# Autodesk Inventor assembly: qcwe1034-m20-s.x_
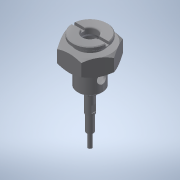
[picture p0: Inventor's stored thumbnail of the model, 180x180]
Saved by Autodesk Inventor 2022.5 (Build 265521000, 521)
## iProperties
Created: 2020-10
Part Number: qcwe1034-m20-s.x_
Material: 一般
Document SubType Name: Assembly
Designer: ImaoCorp
Sending System: SOLIDWORKS 2018-2018316
MC: AMD64
MC_MODEL: Intel64 Family 6 Model 60 Stepping 3, GenuineIntel
OS: Windows_NT
FRU: Parasolid Version 30.0, build 310,  6- 8-2018
FORMAT: text
GUISE: transmit
KEY: qcwe1034-m20-s
FILE: qcwe1034-m20-s.x_t
DATE: Tue Oct  6 10:34:24 2020
Author: ImaoCorp
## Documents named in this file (4)
- X:\14_SW2022-Inv2022\00_全2023-1023新製品(TCC)まで\q\qcwe1034-m20-s\QCWE1034-M20-S.iam
- X:\14_SW2022-Inv2022\00_全2023-1023新製品(TCC)まで\q\qcwe1034-m20-s\qcwe1034-m20-s_01.ipt
- X:\14_SW2022-Inv2022\00_全2023-1023新製品(TCC)まで\q\qcwe1034-m20-s\qcwe1034-m20-s_02.ipt
- X:\14_SW2022-Inv2022\00_全2023-1023新製品(TCC)まで\q\qcwe1034-m20-s\qcwe1034-m20-s_03.ipt
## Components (3 placed, 3 different names)
1. qcwe1034-m20-s_01
2. qcwe1034-m20-s_02
3. qcwe1034-m20-s_03
